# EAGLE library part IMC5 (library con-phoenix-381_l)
Invertierter Mini-Combicon 3.81mm horizontal 5-polig IMC 1,5/5-G-3,81 (ohne Gegenstecker)
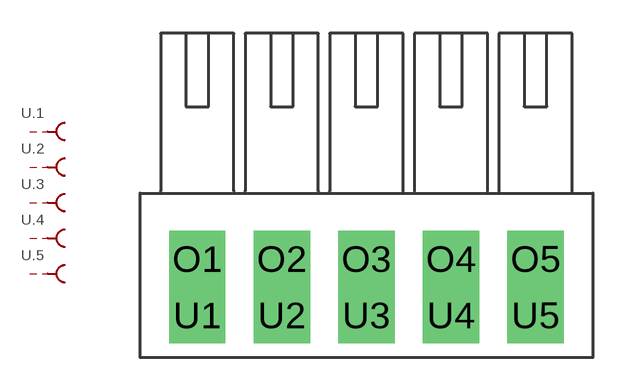
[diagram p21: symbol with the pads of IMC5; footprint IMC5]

Designator prefix -; gates .3=MCBU .2=MCBU .1=MCBU .4=MCBU .5=MCBU

## IMC5  [IMC5]
O1  .1:S  pas
O2  .2:S  pas
O3  .3:S  pas
O4  .4:S  pas
O5  .5:S  pas
U1  .1:SK  pas
U2  .2:SK  pas
U3  .3:SK  pas
U4  .4:SK  pas
U5  .5:SK  pas

## Footprint IMC5 (pad centres in mm)
Mini-Combicon 3.81mm horizontal 5-polig invertiert (ohne Gegenstecker)
drill 1.3 pad 2.54 square: O1 -7.62,1.27; O2 -3.81,1.27; O3 0,1.27; O4 3.81,1.27; O5 7.62,1.27; U1 -7.62,-1.27; U2 -3.81,-1.27; U3 0,-1.27; U4 3.81,-1.27; U5 7.62,-1.27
